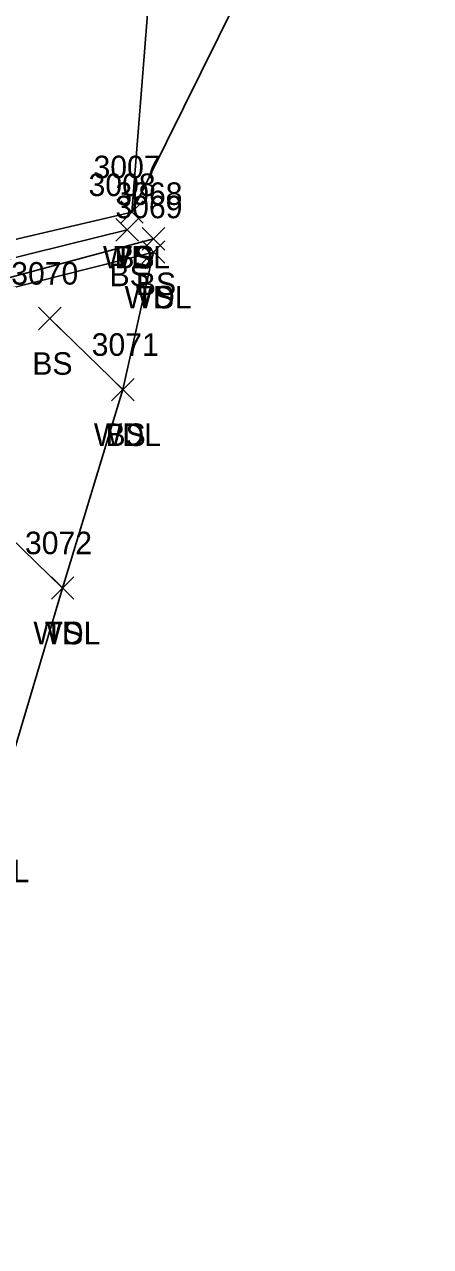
# Model space of a CAD drawing. Extents: x 1678863 to 1683592, y 407783 to 418211.
# Drawn here: x 1680566.7 to 1680602.8, y 415271.2 to 415379.6 of the extents above; entities that cross this region are included whole.
import ezdxf

# ---------------------------------------------------------------- set-up
doc = ezdxf.new("R2010")
doc.units = 0
for name, color, linetype in [('L_A', 7, 'Continuous'), ('L_I', 7, 'Continuous'), ('L_TIC', 7, 'Continuous'), ('LAWA', 7, 'Continuous'), ('LELB', 7, 'Continuous')]:
    doc.layers.add(name, color=color, linetype=linetype)

msp = doc.modelspace()

# ---------------------------------------------------------------- linework, layer by layer
at = {"layer": 'L_TIC'}
for points in [[(1680575.28, 415362), (1680577.28, 415364)], [(1680577.28, 415362), (1680575.28, 415364)], [(1680575.28, 415362), (1680577.28, 415364)], [(1680577.28, 415362), (1680575.28, 415364)], [(1680575.28, 415362), (1680577.28, 415364)], [(1680577.28, 415362), (1680575.28, 415364)], [(1680574.85, 415360.42), (1680576.85, 415362.42)], [(1680576.85, 415360.42), (1680574.85, 415362.42)], [(1680577.19, 415359.63), (1680579.19, 415361.63)], [(1680579.19, 415359.63), (1680577.19, 415361.63)], [(1680577.2, 415358.45), (1680579.2, 415360.45)], [(1680579.2, 415358.45), (1680577.2, 415360.45)], [(1680577.2, 415358.45), (1680579.2, 415360.45)], [(1680579.2, 415358.45), (1680577.2, 415360.45)], [(1680568, 415352.56), (1680570, 415354.56)], [(1680570, 415352.56), (1680568, 415354.56)], [(1680574.48, 415346.24), (1680576.48, 415348.24)], [(1680576.48, 415346.24), (1680574.48, 415348.24)], [(1680574.48, 415346.24), (1680576.48, 415348.24)], [(1680576.48, 415346.24), (1680574.48, 415348.24)], [(1680569.13, 415328.64), (1680571.13, 415330.64)], [(1680571.13, 415328.64), (1680569.13, 415330.64)], [(1680569.13, 415328.64), (1680571.13, 415330.64)], [(1680571.13, 415328.64), (1680569.13, 415330.64)]]:
    msp.add_lwpolyline(points, dxfattribs=at)
at = {"layer": 'LAWA'}
for points in [[(1680595.8, 415422.86), (1680593.17, 415397.19), (1680576.28, 415363)], [(1680578.2, 415359.45), (1680575.48, 415347.24), (1680570.13, 415329.64), (1680563.81, 415308.53), (1680553.46, 415303.21), (1680545.5, 415284.74), (1680553.27, 415271.21)]]:
    msp.add_lwpolyline(points, dxfattribs=at)
at = {"layer": 'LELB'}
for points in [[(1680602.77, 415511.81), (1680588.55, 415474.85), (1680576.23, 415446.79), (1680565.97, 415419.39), (1680554.33, 415388.44), (1680545.73, 415364.19), (1680536.09, 415340.18), (1680525.46, 415304.97), (1680519.4, 415286.41), (1680524.68, 415282.14), (1680532.04, 415285.77), (1680542.28, 415291.47), (1680548.68, 415299.81), (1680553.8, 415323.68), (1680564.17, 415335.4), (1680560.17, 415349.32), (1680559.79, 415354.79), (1680578.2, 415359.45)], [(1680587.11, 415414.35), (1680579.18, 415399.7), (1680576.28, 415363)], [(1680558.79, 415358.91), (1680576.28, 415363)], [(1680575.85, 415361.42), (1680558.96, 415357.24), (1680544.7, 415348.39), (1680539.93, 415338.02), (1680533.97, 415325.19), (1680528.85, 415304.85), (1680531.75, 415305.28), (1680533.8, 415313.69), (1680538.86, 415329.54), (1680546.23, 415344.91), (1680555.7, 415348.01), (1680549.82, 415332.88), (1680543.74, 415311.02), (1680531.45, 415303.42), (1680524.12, 415293.33), (1680523.09, 415289.09), (1680522.05, 415286.15), (1680523.6, 415285.87), (1680525.99, 415291.08), (1680535.33, 415301.88), (1680545.36, 415302.51)], [(1680545.36, 415302.51), (1680551.53, 415325.03), (1680557.9, 415336.32), (1680559.67, 415349.01), (1680558.81, 415355.43), (1680578.19, 415360.63)], [(1680569, 415353.56), (1680575.48, 415347.24)], [(1680564.17, 415335.4), (1680570.13, 415329.64)]]:
    msp.add_lwpolyline(points, dxfattribs=at)

# ---------------------------------------------------------------- texts
at = {"layer": 'L_A'}
for s, p in [('WDL', (1680573.7, 415358)), ('TS', (1680574.69, 415358)), ('BS', (1680574.72, 415358)), ('BS', (1680574.29, 415356.42)), ('BS', (1680576.63, 415355.63)), ('WDL', (1680575.62, 415354.45)), ('TS', (1680576.61, 415354.45)), ('BS', (1680567.44, 415348.56)), ('WDL', (1680572.9, 415342.24)), ('BS', (1680573.93, 415342.24)), ('WDL', (1680567.54, 415324.64)), ('TS', (1680568.54, 415324.64)), ('WDL', (1680561.22, 415303.53))]:
    msp.add_text(s, height=2, dxfattribs=at).set_placement(p)
at = {"layer": 'L_I'}
for s, p in [('3007', (1680572.87, 415366)), ('3007', (1680572.87, 415366)), ('3007', (1680572.87, 415366)), ('3008', (1680572.43, 415364.42)), ('3068', (1680574.81, 415363.63)), ('3069', (1680574.81, 415362.45)), ('3069', (1680574.81, 415362.45)), ('3070', (1680565.57, 415356.56)), ('3071', (1680572.71, 415350.24)), ('3071', (1680572.71, 415350.24)), ('3072', (1680566.79, 415332.64)), ('3072', (1680566.79, 415332.64))]:
    msp.add_text(s, height=2, dxfattribs=at).set_placement(p)

doc.saveas('drawing.dxf')
